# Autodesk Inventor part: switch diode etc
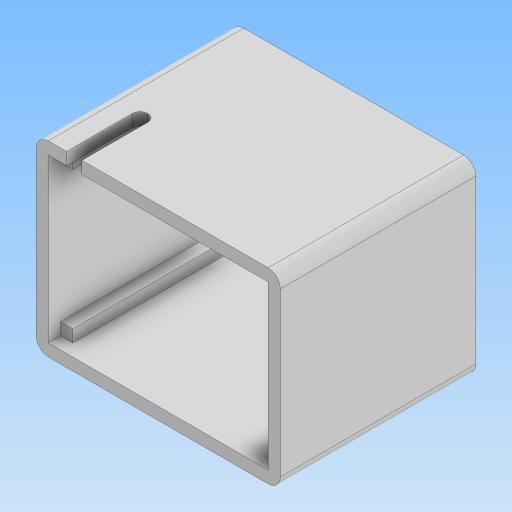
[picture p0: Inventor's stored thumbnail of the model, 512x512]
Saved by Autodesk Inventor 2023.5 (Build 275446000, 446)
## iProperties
Created: 2025-12
Part Number: switch diode etc
Material: Générique
Document SubType Name: Modeling
Designer: admin
Density: 1 g/cm^3
Appearance: Par défaut
Author: admin
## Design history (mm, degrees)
sketch "Esquisse1"
  geometry: L1 (28.6, 5.2)-(28.6, -5.2); L2 (-2.787, 5.2)-(2.787, 5.2); L3 (17.213, 5.2)-(22.787, 5.2); L4 (28.6, -5.2)-(17.213, -5.2); L5 (2.787, -5.2)-(-2.787, -5.2); L6 (-10, 20.648)-(30, 20.648); L7 (30, 20.648)-(30, -10); L8 (30, -10)-(-10, -10); L9 (-10, -10)-(-10, 20.648); L10 (20, 0)-(0, 0); L11 (10, 0)-(10, 20.648); C1 r 3.2 at (10, 13); A1 r 5.9 centre (0, 0) between (-2.787, 5.2) and (-2.787, -5.2); A2 r 5.9 centre (0, 0) between (2.787, -5.2) and (2.787, 5.2); A3 r 5.9 centre (20, 0) between (22.787, -5.2) and (22.787, 5.2); A4 r 5.9 centre (20, 0) between (17.213, 5.2) and (17.213, -5.2); 1 further point
  constraints: 22 end point, 8 point on circle, 6 parallel, 5 centre point, 3 horizontal, 3 perpendicular, 2 midpoint, 2 point on line, 1 coincident
  dimensions: "d2" = 20 distance of L10.start point (0, 0); "d3" = 10.4 distance of L1.start L1.end; "d5" = 0 vertical distance of point (0, 0) L10.start; "d6" = 40 distance of L7.end L8.end; "d7" = 10 distance from line of L10.end L9; "d8" = 10 distance from line of L7 L10.start (derived); "d9" = 10 distance from line of L8 point (0, 0); "d10" = 6.4 diameter of C1; "d11" = 13 vertical distance of point (0, 0) C1.centre
extrude "Extrusion1" new body sketch "Esquisse1" distance "d12" = 2; taper "d13" = 0 deg
sketch "Esquisse2"
  geometry: L1 (-10, -10)-(30, -10) reference; L2 (30, -10)-(30, 20.648) reference; L3 (30, 20.648)-(-10, 20.648) reference; L4 (-10, 20.648)-(-10, -10) reference; L5 (2.787, -5.2)-(-2.787, -5.2) reference; L6 (-2.787, 5.2)-(2.787, 5.2) reference; L7 (22.787, -5.2)-(17.213, -5.2) reference; L8 (17.213, 5.2)-(22.787, 5.2) reference; L9 (-8, 18.648)-(28, 18.648); L10 (28, 18.648)-(28, -8); L11 (28, -8)-(-8, -8); L12 (-8, -8)-(-8, 18.648); C1 r 3.2 at (10, 13) reference; A1 r 5.9 centre (0, 0) between (-2.787, 5.2) and (-2.787, -5.2) reference; A2 r 5.9 centre (0, 0) between (2.787, -5.2) and (2.787, 5.2) reference; A3 r 5.9 centre (20, 0) between (17.213, 5.2) and (17.213, -5.2) reference; A4 r 5.9 centre (20, 0) between (22.787, -5.2) and (22.787, 5.2) reference; 1 further point
  constraints: 8 end point, 2 parallel, 1 horizontal, 1 perpendicular
  dimensions: "d14" = 2 distance between parallel lines of L1 L11; "d15" = 2 distance between parallel lines of L2 L10; "d16" = 2 distance between parallel lines of L4 L12; "d17" = 2 distance between parallel lines of L3 L9
extrude "Extrusion2" join sketch "Esquisse2" distance "d18" = 30; taper "d19" = 0 deg
sketch "Esquisse3"
  geometry: L1 (40, -32)-(0, -32) reference; L2 (5, -32)-(7.5, -32); L3 (7.5, -32)-(7.5, -20); L4 (7.5, -20)-(5, -20); L5 (5, -20)-(5, -32); L6 (0, 0)-(0, -32) reference; 2 further points
  constraints: 8 end point, 2 parallel, 1 horizontal, 1 perpendicular, 1 point on line
  dimensions: "d20" = 2.5 distance of L3.end L4.end; "d21" = 12 distance of L4.end L2.start; "d47" = 5 distance between parallel lines of L6 L5
extrude "Extrusion3" cut sketch "Esquisse3" distance "d22" = 5; taper "d23" = 0 deg
fillet "Congé1" dims "d24" = 1.2
sketch "Esquisse4"
  geometry: L1 (10, -10)-(-30, -10) reference; L2 (10, 20.648)-(10, -10) reference; L3 (-30, 20.648)-(10, 20.648) reference; L4 (-30, -10)-(-30, 20.648) reference; L5 (-2.787, -5.2)-(2.787, -5.2) reference; L6 (2.787, 5.2)-(-2.787, 5.2) reference; L7 (-22.787, -5.2)-(-17.213, -5.2) reference; L8 (-17.213, 5.2)-(-22.787, 5.2) reference; L9 (-25.991, 15.856)-(-23.242, 15.856); L10 (-23.242, 15.856)-(-23.242, 12.744); L11 (-23.242, 12.744)-(-25.991, 12.744); L12 (-25.991, 12.744)-(-25.991, 15.856); L13 (2.122, 12.609)-(2.122, 15.87); L14 (2.122, 15.87)-(4.871, 15.87); L15 (4.871, 15.87)-(4.871, 12.609); L16 (4.871, 12.609)-(2.122, 12.609); C1 r 3.2 at (-10, 13) reference; A1 r 5.9 centre (0, 0) between (-2.787, 5.2) and (-2.787, -5.2) reference; A2 r 5.9 centre (0, 0) between (2.787, -5.2) and (2.787, 5.2) reference; A3 r 5.9 centre (-20, 0) between (-22.787, 5.2) and (-22.787, -5.2) reference; A4 r 5.9 centre (-20, 0) between (-17.213, -5.2) and (-17.213, 5.2) reference; 1 further point
  constraints: 4 other
extrude "Extrusion4" cut sketch "Esquisse4" extent not by distance; stored distance "d25" = 0; taper "d26" = 0 deg
sketch "Esquisse5"
  geometry: L1 (20.428, 12.029)-(20.428, 15.856) reference; L2 (20.428, 15.856)-(21.936, 15.856) reference; L3 (21.936, 15.856)-(21.936, 12.112) reference; L4 (23.949, 12.112)-(23.949, 15.856) reference; L5 (23.949, 15.856)-(25.456, 15.856) reference; L6 (25.456, 15.856)-(25.456, 12.024) reference; L7 (-5.73, 9.87)-(-5.73, 10.916) reference; L8 (-5.73, 10.916)-(-4.869, 10.916) reference; L9 (-4.869, 10.916)-(-4.869, 14.825) reference; L10 (-4.869, 14.825)-(-5.73, 14.825) reference; L11 (-5.73, 14.825)-(-5.73, 15.87) reference; L12 (-5.73, 15.87)-(-2.501, 15.87) reference; L13 (-2.501, 15.87)-(-2.501, 14.825) reference; L14 (-2.501, 14.825)-(-3.362, 14.825) reference; L15 (-3.362, 14.825)-(-3.362, 10.916) reference; L16 (-3.362, 10.916)-(-2.501, 10.916) reference; L17 (-2.501, 10.916)-(-2.501, 9.87) reference; L18 (-2.501, 9.87)-(-5.73, 9.87) reference; L19 (-8, 18.648)-(-8, -8) reference; L20 (-8, -8)-(28, -8) reference; L21 (28, -8)-(28, 18.648) reference; L22 (28, 18.648)-(-8, 18.648) reference; L23 (2.787, -5.2)-(-2.787, -5.2) reference; L24 (-2.787, 5.2)-(2.787, 5.2) reference; L25 (22.787, -5.2)-(17.213, -5.2) reference; L26 (17.213, 5.2)-(22.787, 5.2) reference; L27 (15, 9.5)-(5, 9.5); L28 (5, 9.5)-(5, 16.5); L29 (5, 16.5)-(15, 16.5); L30 (15, 16.5)-(15, 9.5); L31 (28, 18.648)-(-8, 18.648) reference; L32 (15.5, 16.5)-(4.5, 16.5); L33 (4.5, 16.5)-(4.5, 18.648); L34 (4.5, 18.648)-(15.5, 18.648); L35 (15.5, 18.648)-(15.5, 16.5); L36 (15.5, 9.5)-(4.5, 9.5); L37 (4.5, 9.5)-(4.5, 7.5); L38 (4.5, 7.5)-(15.5, 7.5); L39 (15.5, 7.5)-(15.5, 9.5); C1 r 3.2 at (10, 13) reference; A1 r 5.9 centre (0, 0) between (-2.787, 5.2) and (-2.787, -5.2) reference; A2 r 5.9 centre (0, 0) between (2.787, -5.2) and (2.787, 5.2) reference; A3 r 5.9 centre (20, 0) between (17.213, 5.2) and (17.213, -5.2) reference; A4 r 5.9 centre (20, 0) between (22.787, -5.2) and (22.787, 5.2) reference; 11 further points
  constraints: 24 end point, 6 parallel, 3 horizontal, 3 perpendicular, 3 point on line, 2 midpoint, 4 other
  dimensions: "d27" = 7 distance of L27.end L28.end; "d28" = 3.5 distance from line of L27 C1.centre; "d29" = 10 distance of L28.end L29.end; "d30" = 5 distance from line of C1.centre L30 (= 0.5 x d29); "d31" = 2 distance between parallel lines of L27 L38; "d32" = 11 distance of L37.end L38.end; "d33" = 11 distance of L32.start L32.end; "d34" = 5.5 horizontal distance of C1.centre point (4.5, 17.574) (= 0.5 x d33); "d35" = 5.5 horizontal distance of C1.centre point (15.5, 8.5) (= 0.5 x d32)
extrude "Extrusion5" join sketch "Esquisse5" distance "d36" = 10; taper "d37" = 0 deg
sketch "Esquisse6"
  geometry: L1 (22.787, -5.2)-(17.213, -5.2) reference; L2 (17.213, 5.2)-(22.787, 5.2) reference; L3 (2.787, -5.2)-(-2.787, -5.2) reference; L4 (-2.787, 5.2)-(2.787, 5.2) reference; L5 (15.5, 18.648)-(15.5, 16.5) reference; L6 (15.5, 16.5)-(4.5, 16.5) reference; L7 (4.5, 16.5)-(4.5, 18.648) reference; L8 (4.5, 18.648)-(-8, 18.648) reference; L9 (-8, 18.648)-(-8, -8) reference; L10 (-8, -8)-(28, -8) reference; L11 (28, -8)-(28, 18.648) reference; L12 (28, 18.648)-(15.5, 18.648) reference; L13 (-5.73, 9.87)-(-5.73, 10.916) reference; L14 (-5.73, 10.916)-(-4.869, 10.916) reference; L15 (-4.869, 10.916)-(-4.869, 14.825) reference; L16 (-4.869, 14.825)-(-5.73, 14.825) reference; L17 (-5.73, 14.825)-(-5.73, 15.87) reference; L18 (-5.73, 15.87)-(-2.501, 15.87) reference; L19 (-2.501, 15.87)-(-2.501, 14.825) reference; L20 (-2.501, 14.825)-(-3.362, 14.825) reference; L21 (-3.362, 14.825)-(-3.362, 10.916) reference; L22 (-3.362, 10.916)-(-2.501, 10.916) reference; L23 (-2.501, 10.916)-(-2.501, 9.87) reference; L24 (-2.501, 9.87)-(-5.73, 9.87) reference; L25 (20.428, 12.029)-(20.428, 15.856) reference; L26 (20.428, 15.856)-(21.936, 15.856) reference; L27 (21.936, 15.856)-(21.936, 12.112) reference; L28 (23.949, 12.112)-(23.949, 15.856) reference; L29 (23.949, 15.856)-(25.456, 15.856) reference; L30 (25.456, 15.856)-(25.456, 12.024) reference; L31 (15.5, 9.5)-(15.5, 7.5) reference; L32 (15.5, 7.5)-(4.5, 7.5) reference; L33 (4.5, 7.5)-(4.5, 9.5) reference; L34 (4.5, 9.5)-(15.5, 9.5) reference; L35 (4.5, 16.5)-(15.5, 16.5); L36 (15.5, 16.5)-(15.5, 9.5); L37 (15.5, 9.5)-(4.5, 9.5); L38 (4.5, 9.5)-(4.5, 16.5); C1 r 3.2 at (10, 13) reference; C2 r 3.2 at (10, 13) reference; A1 r 5.9 centre (20, 0) between (17.213, 5.2) and (17.213, -5.2) reference; A2 r 5.9 centre (20, 0) between (22.787, -5.2) and (22.787, 5.2) reference; A3 r 5.9 centre (0, 0) between (-2.787, 5.2) and (-2.787, -5.2) reference; A4 r 5.9 centre (0, 0) between (2.787, -5.2) and (2.787, 5.2) reference; 5 further points
  constraints: 8 end point, 2 parallel, 1 horizontal, 1 perpendicular, 4 other
extrude "Extrusion6" join sketch "Esquisse6" distance "d38" = 3; taper "d39" = 0 deg
sketch "Esquisse7"
  geometry: L1 (-8, 18.648)-(-8, -8) reference; L2 (-8, -8)-(-6, -8); L3 (-6, -8)-(-6, -6); L4 (-6, -6)-(-8, -6); L5 (-8, -6)-(-8, -8); L6 (-8, 18.648)-(-6, 18.648); L7 (-6, 18.648)-(-6, 16.648); L8 (-6, 16.648)-(-8, 16.648); L9 (-8, 16.648)-(-8, 18.648); L10 (28, -8)-(28, 18.648) reference; L11 (28, -8)-(26, -8); L12 (26, -8)-(26, -6); L13 (26, -6)-(28, -6); L14 (28, -6)-(28, -8); L15 (28, 18.648)-(26, 18.648); L16 (26, 18.648)-(26, 16.648); L17 (26, 16.648)-(28, 16.648); L18 (28, 16.648)-(28, 18.648); 6 further points
  constraints: 32 end point, 8 parallel, 4 horizontal, 4 perpendicular, 2 point on line
  dimensions: "d40" = 2 distance of L4.end L3.end; "d41" = 2 distance of L7.end L8.end; "d42" = 2 distance of L2.end L3.end; "d43" = 2 distance of L6.end L7.end; "d44" = 2 distance of L12.end L13.end
extrude "Extrusion7" join sketch "Esquisse7" distance "d45" = 28; taper "d46" = 0 deg
fillet "Congé2" dims "d48" = 2
node "Solide1"
node "Boucle projetée1"
node "Boucle projetée2"
node "Boucle projetée3"
node "Boucle projetée4"
other parameters: "d0" = 11.8, "d1" = 11.8, "d4" = 5.2 (= 0.5 x d3)
